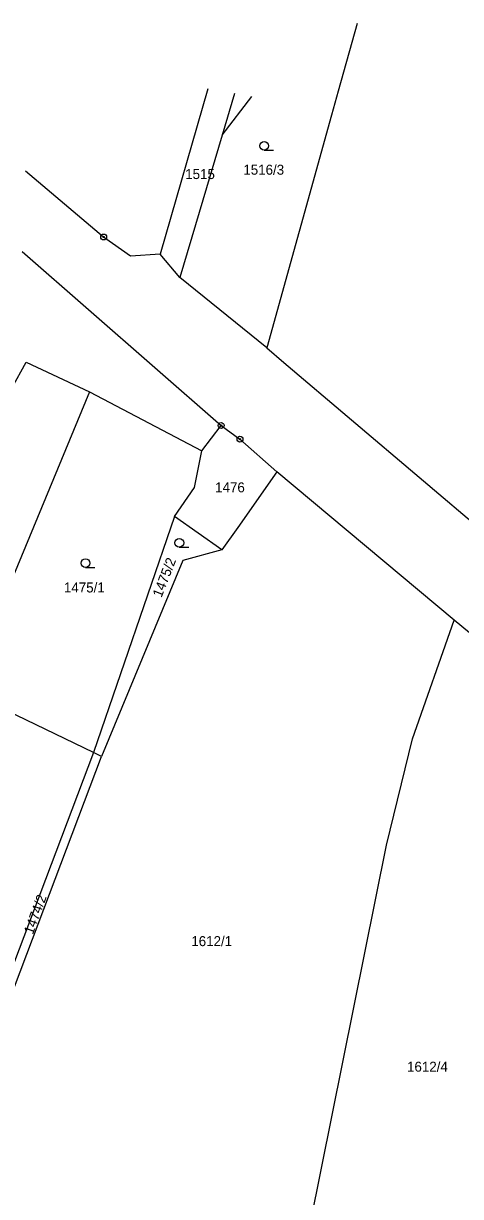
# Model space of a CAD drawing. Extents: x -763296 to -761805, y -1153670 to -1152034.
# Drawn here: x -762623.5 to -762549.1, y -1152400.8 to -1152201.1 of the extents above; entities that cross this region are included whole.
import ezdxf

# ---------------------------------------------------------------- set-up
doc = ezdxf.new("R2010")
doc.units = 0
for name, color, linetype in [('Vrstva 1', 7, 'Continuous'), ('Vrstva 18', 7, 'Continuous'), ('Vrstva 24', 7, 'Continuous'), ('Vrstva 25', 7, 'Continuous'), ('Vrstva 6', 7, 'Continuous')]:
    doc.layers.add(name, color=color, linetype=linetype)

msp = doc.modelspace()

# ---------------------------------------------------------------- linework, layer by layer
at = {"layer": 'Vrstva 1'}
for p, q in [((-762566.73, -1152201.09), (-762569.93, -1152212.6)), ((-762592.14, -1152212.23), (-762600.28, -1152240.38)), ((-762569.93, -1152212.6), (-762571.08, -1152216.7)), ((-762587.59, -1152213.03), (-762589.7, -1152220.12)), ((-762589.7, -1152220.12), (-762584.62, -1152213.55)), ((-762571.08, -1152216.7), (-762582.1, -1152256.33)), ((-762589.7, -1152220.12), (-762596.92, -1152244.36)), ((-762609.88, -1152237.45), (-762623.21, -1152226.25)), ((-762605.32, -1152240.72), (-762609.88, -1152237.45)), ((-762623.75, -1152239.92), (-762589.87, -1152269.52)), ((-762600.28, -1152240.38), (-762605.32, -1152240.72)), ((-762596.92, -1152244.36), (-762600.28, -1152240.38)), ((-762582.1, -1152256.33), (-762596.92, -1152244.36)), ((-762582.1, -1152256.33), (-762579.17, -1152258.81)), ((-762655.97, -1152317.77), (-762623.06, -1152258.78)), ((-762623.06, -1152258.78), (-762612.3, -1152263.79)), ((-762579.17, -1152258.81), (-762541.7, -1152290.61)), ((-762612.3, -1152263.79), (-762633.4, -1152314.71)), ((-762612.3, -1152263.79), (-762593.18, -1152273.87)), ((-762593.18, -1152273.87), (-762589.87, -1152269.52)), ((-762589.87, -1152269.52), (-762586.66, -1152271.86)), ((-762586.66, -1152271.86), (-762580.36, -1152277.43)), ((-762594.42, -1152280.09), (-762593.18, -1152273.87)), ((-762580.36, -1152277.43), (-762587.02, -1152286.88)), ((-762550.16, -1152302.68), (-762580.36, -1152277.43)), ((-762597.81, -1152285.02), (-762594.42, -1152280.09)), ((-762589.77, -1152290.69), (-762597.81, -1152285.02)), ((-762587.02, -1152286.88), (-762589.77, -1152290.69)), ((-762589.77, -1152290.69), (-762596.42, -1152292.52)), ((-762596.42, -1152292.52), (-762610.25, -1152325.9)), ((-762525.16, -1152323.58), (-762550.16, -1152302.68)), ((-762611.61, -1152325.23), (-762633.4, -1152314.71)), ((-762638.33, -1152400.1), (-762610.25, -1152325.9)), ((-762610.25, -1152325.9), (-762611.61, -1152325.23))]:
    msp.add_line(p, q, dxfattribs=at)
at = {"layer": 'Vrstva 24'}
for centre, radius in [((-762609.88, -1152237.45), 0.5), ((-762609.88, -1152237.45), 0.1), ((-762589.87, -1152269.52), 0.5), ((-762589.87, -1152269.52), 0.1), ((-762586.66, -1152271.86), 0.5), ((-762586.66, -1152271.86), 0.1)]:
    msp.add_circle(centre, radius, dxfattribs=at)
at = {"layer": 'Vrstva 25'}
for p, q in [((-762582.54, -1152222.67), (-762580.94, -1152222.67)), ((-762597, -1152290.26), (-762595.4, -1152290.26)), ((-762612.98, -1152293.71), (-762611.38, -1152293.71))]:
    msp.add_line(p, q, dxfattribs=at)
for centre in [(-762582.54, -1152221.92), (-762597, -1152289.51), (-762612.98, -1152292.96)]:
    msp.add_circle(centre, 0.75, dxfattribs=at)
at = {"layer": 'Vrstva 6'}
for p, q in [((-762597.81, -1152285.02), (-762611.61, -1152325.23)), ((-762557.27, -1152322.9), (-762550.16, -1152302.68)), ((-762561.68, -1152340.97), (-762557.27, -1152322.9)), ((-762611.61, -1152325.23), (-762639.37, -1152398.45)), ((-762576.94, -1152416.63), (-762561.68, -1152340.97))]:
    msp.add_line(p, q, dxfattribs=at)

# ---------------------------------------------------------------- texts
at = {"layer": 'Vrstva 18'}
for s, p in [('1515', (-762595.991, -1152227.58)), ('1516/3', (-762586.09, -1152226.84)), ('1476', (-762590.895, -1152280.92)), ('1475/1', (-762616.643, -1152297.96)), ('1612/1', (-762594.952, -1152358.17)), ('1612/4', (-762558.21, -1152379.55))]:
    msp.add_text(s, height=1.7, dxfattribs=at).set_placement(p)
for s, rotation, p in [('1475/2', 68.69764, (-762600.03, -1152298.931)), ('1474/2', 69.95815, (-762621.935, -1152356.297))]:
    msp.add_text(s, height=1.7, rotation=rotation, dxfattribs=at).set_placement(p)

doc.saveas('drawing.dxf')
